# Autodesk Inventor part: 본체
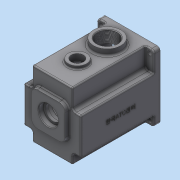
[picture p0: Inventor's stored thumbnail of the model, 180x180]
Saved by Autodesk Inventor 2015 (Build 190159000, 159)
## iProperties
Created: 2016-02
Part Number: 본체
Material: 알루미늄 6061
Document SubType Name: Modeling
Designer: mduedu
Density: 2.7 g/cm^3
Appearance: 기본값
Mass: 1348.73 g
Surface Area: 1142.22 cm^2
Volume: 499.531 cm^3
Author: mduedu
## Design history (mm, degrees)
sketch "스케치1"
  geometry: L1 (-47, -47)-(47, -47); L2 (47, -47)-(47, 63); L3 (47, 63)-(-47, 63); L4 (-47, 63)-(-47, -47); 2 further points
  constraints: 8 end point, 2 parallel, 1 horizontal, 1 midpoint, 1 perpendicular, 1 vertical alignment
  dimensions: "d0" = 94 distance of L2.end L3.end; "d155" = 110 distance of L1.end L2.end; "d156" = 47 distance from line of L1 point (0, 0)
extrude "돌출1" new body sketch "스케치1" distance "d2" = 130; taper "d3" = 0 deg
sketch "스케치3"
  geometry: C1 r 40 at (0, 0); 1 further point
  constraints: 1 centre point, 1 coincident
  dimensions: "d9" = 80 diameter of C1
extrude "돌출3" cut sketch "스케치3" distance "d11" = 121; taper "d12" = 0 deg
sketch "스케치4"
  geometry: C1 r 21 at (0, 11); 1 further point
  constraints: 1 centre point, 1 vertical alignment
  dimensions: "d13" = 21 radius of C1; "d15" = 11 distance of point (0, 0) C1.centre
extrude "돌출4" join sketch "스케치4" distance "d16" = 7; taper "d17" = 0 deg
sketch "스케치5"
  geometry: C1 r 15 at (0, -20); 1 further point
  constraints: 1 centre point, 1 vertical alignment
  dimensions: "d18" = 15 radius of C1; "d20" = 20 distance of point (0, 0) C1.centre
extrude "돌출5" join sketch "스케치5" distance "d21" = 7; taper "d22" = 0 deg
sketch "스케치6"
  geometry: L1 (-28, -17)-(28, -17); L2 (28, -17)-(28, 39); L3 (28, 39)-(-28, 39); L4 (-28, 39)-(-28, -17); L5 (-28, -17)-(28, 39); L6 (28, -17)-(-28, 39); C1 r 28 at (0, 11); A1 r 21 centre (0, 11) between (8.978, -7.984) and (-8.978, -7.984) reference; 1 further point
  constraints: 12 end point, 2 midpoint, 2 parallel, 2 tangent, 1 centre point, 1 coincident, 1 horizontal, 1 perpendicular
  dimensions: "d23" = 56 diameter of C1
extrude "돌출6" join sketch "스케치6" distance "d25" = 7; taper "d26" = -3 deg
hole "구멍1" diameter "d29" = 35; stored, may be unused: countersink angle "d33" = 90 deg, drill point angle "d35" = 0 deg; dims "d27" = 10, "d28" = 10, "d30" = 6, "d31" = 4, "d32" = 2, "d34" = 10
hole "구멍2" diameter "d38" = 22; stored, may be unused: countersink angle "d42" = 90 deg, drill point angle "d44" = 0 deg; dims "d36" = 10, "d37" = 10, "d39" = 6, "d40" = 4, "d41" = 2, "d43" = 7
hole "구멍3" diameter "d47" = 19; stored, may be unused: countersink angle "d51" = 90 deg, drill point angle "d53" = 0 deg; dims "d45" = 10, "d46" = 10, "d48" = 6, "d49" = 4, "d50" = 2, "d52" = 1
hole "구멍4" diameter "d56" = 32; stored, may be unused: countersink angle "d60" = 90 deg, drill point angle "d62" = 0 deg; dims "d57" = 6, "d58" = 4, "d59" = 2, "d61" = 8, "d220" = 10, "d221" = 10
hole "구멍5" diameter "d65" = 25; stored, may be unused: countersink angle "d69" = 90 deg, drill point angle "d71" = 0 deg; dims "d63" = 10, "d64" = 10, "d66" = 6, "d67" = 4, "d68" = 2, "d70" = 8
fillet "모깎기2" dims "d73" = 0.3
fillet "모깎기3" dims "d74" = 2
chamfer "모따기1" distance "d75" = 1; stored, may be unused: second distance "d76" = 2, angle "d77" = 45 deg
fillet "모깎기4" dims "d78" = 3
sketch "스케치16"
  geometry: L1 (-23, 32.726)-(23, 32.726); L2 (23, 32.726)-(23, 53); L3 (23, 53)-(-23, 53); L4 (-23, 53)-(-23, 32.726); L5 (-47, 63)-(47, 63) reference; 3 further points
  constraints: 8 end point, 2 parallel, 1 horizontal, 1 midpoint, 1 perpendicular, 1 vertical alignment, 2 other
  dimensions: "d160" = 46 distance of L2.end L3.end; "d163" = 10 distance between parallel lines of L3 L5
extrude "돌출15" cut sketch "스케치16" stored distance "d164" = 10; taper "d165" = 0 deg
fillet "모깎기5" dims "d79" = 2
fillet "모깎기15" dims "d166" = 5
sketch "스케치7"
  geometry: L1 (-23, 48)-(-23, 35.228) reference; L2 (23, 35.228)-(23, 48) reference; L3 (18, 53)-(-18, 53) reference; L4 (47, 63)-(47, -47) reference; L5 (47, -47)-(-47, -47) reference; L6 (-47, -47)-(-47, 63) reference; L7 (-47, 63)-(47, 63) reference; L8 (-26, 48)-(-26, 35.228); L9 (26, 35.228)-(26, 48); L10 (18, 56)-(-18, 56); C1 r 43 at (0, 0); A1 r 5 centre (-18, 48) between (-18, 53) and (-23, 48) reference; A2 r 5 centre (-28, 35.228) between (-24.889, 31.314) and (-23, 35.228) reference; A3 r 40 centre (0, 0) between (-24.889, 31.314) and (24.889, 31.314) reference; A4 r 5 centre (28, 35.228) between (23, 35.228) and (24.889, 31.314) reference; A5 r 5 centre (18, 48) between (23, 48) and (18, 53) reference; A6 r 8 centre (-18, 48) between (-18, 56) and (-26, 48); A7 r 2 centre (-28, 35.228) between (-26.756, 33.662) and (-26, 35.228); A8 r 43 centre (0, 0) between (-26.756, 33.662) and (26.756, 33.662); A9 r 2 centre (28, 35.228) between (26, 35.228) and (26.756, 33.662); A10 r 8 centre (18, 48) between (26, 48) and (18, 56); 1 further point
  constraints: 10 point on circle, 6 centre point, 6 end point, 1 coincident, 7 other
  dimensions: "d80" = 86 diameter of C1; "d167" = 3 distance between parallel lines of L3 L10
extrude "돌출7" cut sketch "스케치7" distance "d83" = 9; taper "d84" = 0 deg
sketch "스케치8" dims "d168" = 36
  geometry: L1 (-36, 4)-(-39.799, 4); L2 (-36, -4)-(-39.799, -4); A1 r 4 centre (-36, 0) between (-36, 4) and (-36, -4); A2 r 40 centre (0, 0) between (-24.889, 31.314) and (24.889, 31.314) reference; A3 r 40 centre (0, 0) between (-39.799, 4) and (-39.799, -4); 2 further points
  constraints: 5 point on circle, 4 end point, 2 centre point, 2 coincident, 2 horizontal alignment, 2 tangent, 1 horizontal, 1 parallel, 2 other
  dimensions: "d169" = 4 radius of A1
extrude "돌출9" join sketch "스케치8" stored distance "d89" = 9; taper "d90" = 0 deg
fillet "모깎기6" dims "d91" = 3.5
node "작업 평면1"
sketch "스케치9"
  geometry: L1 (47, 63)-(33, 63); L2 (33, 63)-(33, 30); L3 (33, 30)-(47, 30); L4 (47, 30)-(47, 63); L5 (47, 63)-(-47, 63) reference; L6 (47, -47)-(47, 63) reference; A1 r 40 centre (0, 0) between (-39.148, -8.214) and (39.148, -8.214) reference; 1 further point
  constraints: 8 end point, 2 parallel, 1 coincident, 1 horizontal, 1 perpendicular
  dimensions: "d95" = 33 distance from line of L2 point (0, 0); "d96" = 30 distance from line of L3 point (0, 0)
extrude "돌출10" cut sketch "스케치9" distance "d97" = 110; taper "d98" = 0 deg
extrude "돌출21" cut sketch "스케치9" stored distance "d217" = 10; taper "d218" = 0 deg
sketch "스케치11" dims "d20" = 20
  geometry: L1 (-40, -40)-(40, -40); L2 (40, -40)-(40, 56); L3 (40, 56)-(-40, 56); L4 (-40, 56)-(-40, -40); L5 (-47, -47)-(47, -47) reference; L6 (47, 63)-(-47, 63) reference; L7 (-47, 63)-(-47, -47) reference; C1 r 3.5 at (-40, 56); C2 r 3.5 at (40, 56); C3 r 3.5 at (40, -40); C4 r 3.5 at (-40, -40); 1 further point
  constraints: 8 end point, 4 centre point, 4 coincident, 3 equal radius, 2 parallel, 1 horizontal, 1 perpendicular
  dimensions: "d109" = 80 distance of L2.end L3.end; "d112" = 7 diameter of C1; "d157" = 7 distance from line of L1.start L5; "d158" = 7 distance between parallel lines of L6 L3; "d159" = 7 distance from line of L7 L3.end
extrude "돌출12" cut sketch "스케치11" stored distance "d113" = 63; taper "d114" = 0 deg
fillet "모깎기7" dims "d115" = 5, "d187" = 5
fillet "모깎기8" dims "d116" = 5
fillet "모깎기18" dims "d219" = 2
fillet "모깎기12" dims "d120" = 2
fillet "모깎기13" dims "d121" = 2
sketch "스케치12"
  geometry: 3 further points
  constraints: 2 horizontal alignment
hole "구멍6" sketch "스케치12" at (36, 0), (-36, 0) diameter "d122" = 3.242; stored, may be unused: countersink angle "d126" = 90 deg, drill point angle "d128" = 120 deg; dims "d123" = 7, "d124" = 4, "d125" = 2, "d127" = 9
fillet "모깎기14" dims "d147" = 10
chamfer "모따기4" distance "d151" = 1; stored, may be unused: second distance "d152" = 2, angle "d153" = 45 deg
sketch "스케치20"
  geometry: L1 (73, -12)-(73, -130) reference; L2 (84, -8)-(77, -8) reference; L3 (84, 0)-(84, -8) reference; L4 (84, 0)-(0, 0) reference; L5 (7, -8)-(0, -8) reference; L6 (11, -130)-(11, -12) reference; L7 (0, -8)-(0, 0) reference; L8 (73, -130)-(11, -130) reference; L9 (42, 0)-(42, -130); C1 r 10 at (42, -89); A1 r 4 centre (77, -12) between (77, -8) and (73, -12) reference; A2 r 4 centre (7, -12) between (11, -12) and (7, -8) reference
  constraints: 2 end point, 1 centre point, 1 midpoint, 1 point on line
  dimensions: "d189" = 20 diameter of C1; "d190" = 41 distance from line of C1.centre L8
extrude "돌출19" cut sketch "스케치20" stored distance "d191" = 10; taper "d192" = 0 deg
sketch "스케치18"
  geometry: C1 r 15 at (42, -89); C2 r 10 at (42, -89) reference; 1 further point
  constraints: 1 centre point, 1 concentric
  dimensions: "d174" = 30 diameter of C1
extrude "돌출17" join sketch "스케치18" distance "d175" = 5; taper "d176" = 0 deg
fillet "모깎기16" dims "d177" = 2
sketch "스케치19"
  geometry: C1 r 10 at (18, 80) reference; C2 r 15 at (18, 80); 1 further point
  constraints: 1 centre point, 1 coincident
  dimensions: "d178" = 30 diameter of C2
extrude "돌출18" cut sketch "스케치19" distance "d181" = 5; taper "d182" = 0 deg
chamfer "모따기5" distance "d183" = 0.5; stored, may be unused: second distance "d184" = 2, angle "d185" = 45 deg
sketch "스케치21"
  geometry: L1 (-12, 14)-(-130, 14) reference; L2 (-8, 0)-(-8, 10) reference; L3 (0, 0)-(0, 100) reference; L4 (-8, 100)-(0, 100) reference; L5 (-8, 74)-(-8, 100) reference; L6 (-130, 70)-(-12, 70) reference; L7 (-130, 14)-(-130, 70) reference; L8 (0, 0)-(-8, 0) reference; L9 (-130, 14)-(-130, 70) reference; L10 (27.4, 42)-(-164.4, 42) reference; A1 r 4 centre (-12, 74) between (-12, 70) and (-8, 74) reference; A2 r 4 centre (-12, 10) between (-8, 10) and (-12, 14) reference; 3 further points
  constraints: 1 coincident, 1 point on line, 1 other
  dimensions: "d222" = 65 distance from line of point (-65, 42) L9
feature "엠보싱2" sketch "스케치21" dims "d20" = 20, "d193" = 0.5, "d194" = 0
sketch "스케치22"
  geometry: L1 (73, -12)-(73, -130) reference; L2 (84, -8)-(77, -8) reference; L3 (84, 0)-(84, -8) reference; L4 (84, 0)-(0, 0) reference; L5 (7, -8)-(0, -8) reference; L6 (11, -130)-(11, -12) reference; L7 (0, -8)-(0, 0) reference; L8 (73, -130)-(11, -130) reference; L9 (42, -130)-(42, 0); C1 r 17 at (42, -89) reference; C2 r 22.5 at (42, -40); A1 r 4 centre (77, -12) between (77, -8) and (73, -12) reference; A2 r 4 centre (7, -12) between (11, -12) and (7, -8) reference
  constraints: 2 end point, 1 centre point, 1 midpoint, 1 point on line
  dimensions: "d195" = 45 diameter of C2; "d197" = 40 distance from line of C2.centre L4
extrude "돌출20" join sketch "스케치22" distance "d198" = 10; taper "d199" = 0 deg
fillet "모깎기17" dims "d200" = 3
hole "구멍7" diameter "d203" = 33.376; stored, may be unused: countersink angle "d207" = 90 deg, drill point angle "d209" = 118 deg; dims "d204" = 6, "d205" = 4, "d206" = 2, "d208" = 8, "d223" = 10, "d224" = 10
chamfer "모따기6" distance "d210" = 1; stored, may be unused: second distance "d211" = 2, angle "d212" = 45 deg
fillet "모깎기19" dims "d225" = 2
node "솔리드1"
pattern_circular "원형 패턴1" dims angle "d93" = 360 deg
mirror "대칭1"
mirror "대칭2"
node "투영된 루프1"
node "투영된 루프2"
node "투영된 루프3"
node "절단 모서리 투영3"
